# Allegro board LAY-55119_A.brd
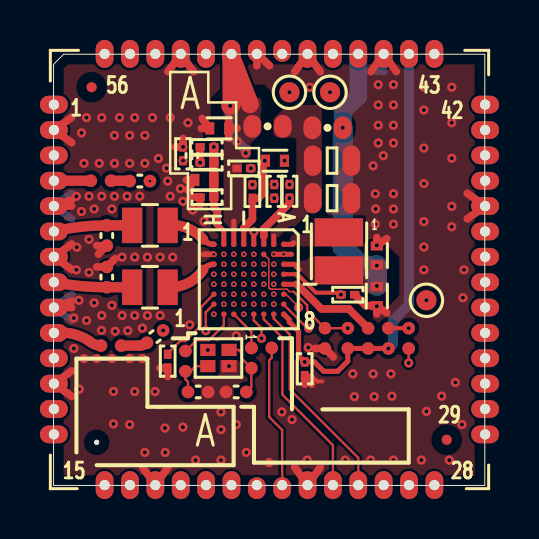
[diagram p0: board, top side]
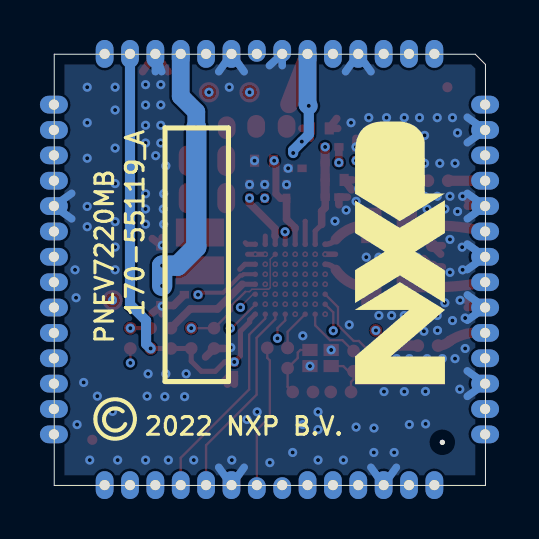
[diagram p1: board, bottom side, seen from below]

Outline 21.59 x 21.59 mm; copper layers: TOP, L2_GND_1, L3_INT_1, L4_INT_2, L5_GND_2, BOTTOM. Coordinates in mm from the lower left corner of the outline.
Outline path: 0,21.08 0,0 21.59,0 21.59,21.59 0.51,21.59 0,21.08

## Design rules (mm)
constraint set DEFAULT: min track width 0.117
net group USB: nets ATX_C ATX_D
net group PWR: nets TCVCM TXVCASC VBAT VDDC VDDIO VDDNV VDDPA VREF

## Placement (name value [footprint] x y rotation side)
C1  18PF  [CC0402_25]  9.14 4.68 180 top
C2  18PF  [CC0402_25]  7.24 4.68 0 top
C5  0.1uF  [CC0201]  5.71 6.22 270 top
C7  1000pF  [CC0402_25]  5.08 7.45 217.3 top
C8  0.1uF  [CC0201]  12.57 5.84 270 top
C9  0.22uF  [CC0201]  14.73 9.55 0 top
C10  4.7uF  [CC0402_TOL0P15]  16.19 9.48 270 top
C11  0.22uF  [CC0201]  11.81 14.73 90 top
C12  560pF  [CC0402_25]  2.67 10.43 90 top
C13  4.7uF  [CC0402_TOL0P15]  16.19 11.51 90 top
C14  560pF  [CC0402_25]  2.67 12.51 270 top
C15  100pF  [CC0201]  7.68 14.43 180 top
C16  0.1uF  [CC0201]  11.05 14.72 90 top
C17  1uf  [CC0201]  9.96 14.72 90 top
C19  22uF  [CC0805_OV]  13.94 14.38 0 top
C20  4.7uF  [CC0402_TOL0P15]  7.55 15.3 180 top
C21  1000pF  [CC0402_25]  4.32 15.24 180 top
C22  100pF  [CC0201]  9.52 15.88 0 top
C23  100pF  [CC0201]  7.68 16.16 0 top
C24  4.7uF  [CC0402_TOL0P15]  11.09 16.26 0 top
C26  0.22uF  [CC0201]  6.48 16.61 90 top
C27  22uF  [CC0805_OV]  13.94 16.26 0 top
C28  0.22uF  [CC0201]  7.68 16.95 0 top
C29  4.7uF  [CC0402_TOL0P15]  8.29 17.88 180 top
L1  160nH  [IND0805HQ]  4.83 9.92 180 top
L2  1.0uH  [IND_1008_SMD]  14.29 11.72 270 top
L3  160nH  [IND0805HQ]  4.83 13.02 180 top
NOREF  -  [unnamed]  1.9 19.94 180 top
NOREF#2  -  [#2]  8.79 5.97 90 top
NOREF#3  -  [unnamed]  19.68 2.29 180 top
NOREF#4  -  [#2]  -53.92 -161.42 0 top
NOREF#5  -  [#2]  16.19 11.04 90 top
NOREF#6  -  [#2]  8.12 15.62 0 top
NOREF#7  -  [#2]  21.61 0.02 90 top
NOREF#8  -  [#2]  7.47 8.02 90 top
NOREF#9  -  [unnamed]  2.16 2.16 270 top
NOREF#10  -  [#2]  7.72 6.78 0 top
NOREF#11  -  [#2]  8.87 18.2 0 top
NOREF#12  -  [#2]  9.28 15.62 90 top
NOREF#13  -  [#2]  9.1 7.03 90 top
NOREF#14  -  [#2]  10.61 16.26 0 top
NOREF#15  -  [#2]  -267.27 261.62 0 top
NOREF#16  -  [#2]  10.18 0.02 0 top
NOREF#17  -  [#2]  -294.83 -257.94 0 top
NOREF#18  -  [#2]  0 0 0 top
NOREF#19  -  [#2]  -27.72 -40.64 0 top
NOREF#20  -  [#2]  21.61 5.1 90 top
NOREF#21  -  [#2]  15.86 10.06 0 top
NOREF#22  -  [#2]  9.1 7.03 0 top
NOREF#23  -  [#2]  11.66 15.93 90 top
NOREF#24  -  [#2]  10.51 15.93 0 top
NOREF#25  -  [#2]  2.16 2.16 0 top
NOREF#26  -  [#2]  0.02 0.02 0 top
NOREF#27  -  [#2]  17.01 10.06 90 top
NOREF#28  -  [#2]  16.51 10.94 0 top
NOREF#29  -  [#2]  7.07 15.3 0 top
NOREF#30  -  [#2]  7.47 8.02 0 top
NOREF#31  -  [#2]  21.61 2.56 90 top
NOREF#32  -  [#2]  17.66 10.94 90 top
NOREF#33  -  [#2]  21.59 0 90 top
NOREF#34  -  [#2]  7.82 17.88 0 top
NOREF#35  -  [#2]  10.02 18.2 90 top
NOREF#36  -  [#2]  16.19 9.01 90 top
NOREF#37  -  [#2]  18.54 3.3 180 bottom
NOREF#38  -  [#2]  2.03 5.08 90 bottom
NOREF#39  -  [#2]  16.55 17.39 270 bottom
P1  PN76xx-M  [MODULE56_1P52_25X25MM_NSP]  10.81 10.81 0 top
R1  0  [RC0402_25]  10.41 6.89 180 top
R2  0  [RC0402_25]  2.88 7 180 top
R3  0  [RC0402_25]  2.37 15.26 180 top
R4  0  [RC0603_OV]  10.72 17.98 180 top
R5  0  [RC0402_25]  15.75 7.37 270 top
R6  0  [RC0402_25]  13.59 7.37 90 top
R7  0  [RC0402_25]  14.73 7.37 90 top
R8  0  [RC0603_OV]  13.72 17.91 180 top
R9  10.0K  [RC0402_25]  16.76 7.37 90 top
R10  0  [RC0402_25]  17.78 7.37 270 top
R11  0  [RC0402_25]  9.91 6.38 270 top
R12  0  [RC0402_25]  6.6 6.22 270 top
TP1  -  [TPAD_040]  13.84 19.68 180 top
TP2  -  [TPAD_040]  11.81 19.68 180 top
TP3  -  [TPAD_040]  18.67 9.27 180 top
U1  PN7220  [VFBGA64_0P5_4P6X4P6]  9.77 10.32 270 top
Y1  27.12MHz  [XTAL4_1P6X1P2]  8.25 6.38 180 top

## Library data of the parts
C1 C2 C7 C10 C12-C14 C19-C21 C24 C27 C29 = CAP_NP
C5 C8 C16 = CAP_NP: Tolerance: TOLERANCE; User Part Number: 150-80059
C9 C11 C26 C28 = CAP_NP: Tolerance: TOLERANCE; User Part Number: 150-79474
C15 C22 C23 = CAP_NP: Tolerance: TOLERANCE; User Part Number: 150-75742
C17 = CAP_NP: Tolerance: TOLERANCE; User Part Number: 150-79855
L1 L3 = INDUCTOR: tolerance: 5%
L2 = INDUCTOR: tolerance: 20%
P1 = TP_RECT_56P
R1-R8 R10-R12 = RES
R9 = RES: tolerance: 5%
TP1-TP3 = TESTLOOP
U1 = PN7220_BGA64_A
Y1 = XTAL_13

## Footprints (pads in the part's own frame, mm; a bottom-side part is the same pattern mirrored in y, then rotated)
CC0201
  rect 0.47x0.381 smd: 1(-0.343,0) 2(0.343,0)
CC0402_25
  round 0.635 smd: 1(-0.508,0) 2(0.508,0)
CC0402_TOL0P15
  rect 0.457x0.61 smd: 1(-0.475,0) 2(0.475,0)
CC0805_OV
  oval 0.889x1.524 smd: 1(-0.965,0) 2(0.965,0)
IND0805HQ
  rect 1.016x1.778 smd: 1(-0.889,0) 2(0.889,0)
IND_1008_SMD
  rect 1.397x2.413 smd: 1(-0.95,0) 2(0.95,0)
MODULE56_1P52_25X25MM_NSP
  oval 1.397x0.889 hole 0.508: 1(-10.795,8.255) 2(-10.795,6.985) 3(-10.795,5.715) 4(-10.795,4.445) 5(-10.795,3.175) 6(-10.795,1.905) 7(-10.795,0.635) 8(-10.795,-0.635) 9(-10.795,-1.905) 10(-10.795,-3.175) 11(-10.795,-4.445) 12(-10.795,-5.715) 13(-10.795,-6.985) 14(-10.795,-8.255) 29(10.795,-8.255) 30(10.795,-6.985) 31(10.795,-5.715) 32(10.795,-4.445) 33(10.795,-3.175) 34(10.795,-1.905) 35(10.795,-0.635) 36(10.795,0.635) 37(10.795,1.905) 38(10.795,3.175) 39(10.795,4.445) 40(10.795,5.715) 41(10.795,6.985) 42(10.795,8.255)
  oval 0.889x1.397 hole 0.508: 15(-8.255,-10.795) 16(-6.985,-10.795) 17(-5.715,-10.795) 18(-4.445,-10.795) 19(-3.175,-10.795) 20(-1.905,-10.795) 23(1.905,-10.795) 24(3.175,-10.795) 25(4.445,-10.795) 26(5.715,-10.795) 27(6.985,-10.795) 28(8.255,-10.795) 43(8.255,10.795) 44(6.985,10.795) 45(5.715,10.795) 46(4.445,10.795) 47(3.175,10.795) 48(1.905,10.795) 51(-1.905,10.795) 52(-3.175,10.795) 53(-4.445,10.795) 54(-5.715,10.795) 55(-6.985,10.795) 56(-8.255,10.795)
  oval 0.889x1.092 hole 0.508: 21(-0.635,-10.795) 22(0.635,-10.795) 49(0.635,10.795) 50(-0.635,10.795)
RC0402_25
  round 0.635 smd: 1(-0.508,0) 2(0.508,0)
RC0603_OV
  oval 0.889x1.143 smd: 1(-0.762,0) 2(0.762,0)
TPAD_040
  round 1.016 smd: 1(0,0)
unnamed
  round 0.508 smd: (0,0)
VFBGA64_0P5_4P6X4P6
  round 0.279 smd: A1(-1.75,1.75) A2(-1.25,1.75) A3(-0.75,1.75) A4(-0.25,1.75) A5(0.25,1.75) A6(0.75,1.75) A7(1.25,1.75) A8(1.75,1.75) B1(-1.75,1.25) B2(-1.25,1.25) B3(-0.75,1.25) B4(-0.25,1.25) B5(0.25,1.25) B6(0.75,1.25) B7(1.25,1.25) B8(1.75,1.25) C1(-1.75,0.75) C2(-1.25,0.75) C3(-0.75,0.75) C4(-0.25,0.75) C5(0.25,0.75) C6(0.75,0.75) C7(1.25,0.75) C8(1.75,0.75) D1(-1.75,0.25) D2(-1.25,0.25) D3(-0.75,0.25) D4(-0.25,0.25) D5(0.25,0.25) D6(0.75,0.25) D7(1.25,0.25) D8(1.75,0.25) E1(-1.75,-0.25) E2(-1.25,-0.25) E3(-0.75,-0.25) E4(-0.25,-0.25) E5(0.25,-0.25) E6(0.75,-0.25) E7(1.25,-0.25) E8(1.75,-0.25) F1(-1.75,-0.75) F2(-1.25,-0.75) F3(-0.75,-0.75) F4(-0.25,-0.75) F5(0.25,-0.75) F6(0.75,-0.75) F7(1.25,-0.75) F8(1.75,-0.75) G1(-1.75,-1.25) G2(-1.25,-1.25) G3(-0.75,-1.25) G4(-0.25,-1.25) G5(0.25,-1.25) G6(0.75,-1.25) G7(1.25,-1.25) G8(1.75,-1.25) H1(-1.75,-1.75) H2(-1.25,-1.75) H3(-0.75,-1.75) H4(-0.25,-1.75) H5(0.25,-1.75) H6(0.75,-1.75) H7(1.25,-1.75) H8(1.75,-1.75)
XTAL4_1P6X1P2
  rect 0.762x0.61 smd: 1(-0.531,-0.405) 2(0.531,-0.405) 3(0.531,0.405) 4(-0.531,0.405)

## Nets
GND: C1.2 C2.2 C5.2 C8.2 C9.2 C10.2 C11.2 C12.2 C13.2 C14.2 C15.2 C16.2 C17.2 C19.2 C20.2 C22.2 C24.2 C26.2 C27.2 C29.2 P1.2 P1.5 P1.7 P1.9 P1.12 P1.17 P1.23 P1.38 P1.45 P1.48 P1.50 P1.53 R6.1 U1.A2 U1.B2 U1.C3 U1.D3 U1.E3 U1.F3 U1.F4 U1.G3 U1.H2 Y1.2 Y1.4
PVDDOUT: R5.1 U1.A5
VBAT: C17.1 C24.1 P1.49 U1.E1
VBATPWR: C10.1 C13.1 L2.2 P1.46 R8.1 U1.A3
VDDBOOST: C19.1 C27.1 R4.1 R8.2 U1.B1
VDDC: C11.1 TP1.1(PIN1) U1.C1
VDDIO: C8.1 P1.44 R5.2 R7.1 R9.1 U1.A8
VDDNV: C9.1 TP3.1(PIN1) U1.A4
VDDPA: C15.1 C20.1 C23.2 C28.2 P1.52 U1.G1
ATX_A: P1.34 U1.E6
ATX_B: P1.35 U1.E5
ATX_C: P1.36 U1.D6
ATX_D: P1.37 U1.D5
AUX1: P1.18 U1.G7
AUX2: P1.19 U1.F7
BOOST_LX: L2.1 U1.A1
C_RXN: C21.2 R3.1
C_RXP: C7.2 R2.1
CLK_IN: P1.22 R1.1
CT_CLK: P1.56 U1.E4
CT_INT: P1.54 U1.C4
CT_IO: P1.55 U1.D4
DWL_REQ: P1.27 U1.A7
GPIO0: P1.28 U1.E8
GPIO1: P1.31 U1.D8
GPIO2: P1.29 U1.E7
GPIO3: P1.30 U1.D7
GPIO4: P1.32 U1.C5
GPIO5: P1.33 U1.B5
HOSTIF_SEL0: P1.20 U1.C7
HOSTIF_SEL1: P1.21 U1.C6
I2CM_SCL: P1.40 U1.B6
I2CM_SDA: P1.39 U1.A6
IRQ: P1.26 U1.B7
MOD_RXN: P1.4 R3.2
MOD_RXP: P1.10 R2.2
MOD_TX1: C14.1 L3.2 P1.6
MOD_TX2: C12.1 L1.2 P1.8
MOD_VEN: P1.43 R10.2
NO_AD1: P1.1 U1.E2
NO_TEST: R6.2 R7.2 U1.C2
NO_USB_VBUS: P1.47 U1.D1
PRD1: P1.41 U1.B4
PRD2: P1.42 U1.G4
RXN: C21.1 U1.H4
RXP: C7.1 U1.H5
SPIM_MISO: P1.16 U1.F6
SPIM_MOSI: P1.13 U1.F5
SPIM_NSS: P1.15 U1.G6
SPIM_SCLK: P1.14 U1.G5
SWDCLK: P1.24 U1.C8
SWDIO: P1.25 U1.B8
TCVCM: C26.1 U1.G2
TX1: L3.1 U1.H1
TX2: L1.1 U1.H3
TXVCASC: C23.1 C28.1 U1.F2
VEN: R9.2 R10.1 U1.B3
VMID: C5.1 U1.H6
VREF: C16.1 TP2.1(PIN1) U1.D2
VTUNE0: P1.3 U1.H8
VTUNE1: P1.11 U1.H7
VUP: C22.1 C29.1 P1.51 R4.2 U1.F1
XTAL1: R1.2 R11.1 U1.F8
XTAL2: R12.1 U1.G8(XTAL2)
N26294688: C1.1 R11.2 Y1.1
N26294692: C2.1 R12.2 Y1.3

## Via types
v1: diameter 0.457, hole 0.203, TOP to BOTTOM, 140 vias
v2: diameter 0.457, hole 0.206, TOP to BOTTOM, 28 vias
v3: diameter 0.279, hole 0.13, TOP to L2_GND_1, 42 vias
v4: diameter 0.254, hole 0.13, L2_GND_1 to L3_INT_1, 33 vias
v5: diameter 0.279, hole 0.13, L3_INT_1 to L4_INT_2, 16 vias

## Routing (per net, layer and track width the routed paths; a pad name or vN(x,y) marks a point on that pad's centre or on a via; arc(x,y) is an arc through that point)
GND: length 140.5
  TOP w0.203: C8.2 12.92,5.5 13.21,5.21 13.46,5.21
  TOP w0.254: 11.91,11.57 v3(11.52,11.57) v3(11.02,11.57)
  TOP w0.279: v3(8.02,11.57) 7.51,11.57
  TOP w0.381: 6.66,15.3 C20.2 6.7,14.8 ; 2.24,11.58 C14.2 2.16,12.01 ; 13.35,20.72 P1.48 12.08,20.72 ; 13.35,0.91 P1.23 12.08,0.91 ; 16.68,12.36 C13.2 16.19,12.41 ; 5.73,0.91 P1.17 4.46,0.91 ; 13.08,6.86 R6.1 14.01,6.43 ; 0.91,12.08 P1.7 0.91,10.81 ; 7.4,17.88 C29.2 7.45,18.37 ; C9.2 15.62,9.01 C10.2 ; 12.92,5.07 C8.2 12.57,5.07 ; 5.71,5.45 C5.2 5.33,5.88 ; 0.91,9.22 P1.9 0.91,8.91 ; 5.73,20.72 P1.53 7,20.72 ; 20.72,13.35 P1.38 20.72,14.62 ; 0.91,5.73 P1.12 0.91,4.46 ; 16.19,8.59 C10.2 ; C10.2 16.68,8.63 ; 17.16,20.72 P1.45 15.89,20.72 ; 0.91,13.99 P1.5 0.91,14.3 ; 10.18,21.02 P1.50 10.81,21.02 ; 2.16,10.94 C12.2 3.09,11.36 ; 6.48,17.38 v2(6.48,16.95) 6.1,16.95 ; 6.91,14.43 C15.2 7.34,14.05 ; 0.91,17.16 P1.2 0.91,18.43
  L2_GND_1 w0.381: 0.91,12.08 P1.7 0.91,10.81 ; 13.35,20.72 P1.48 12.08,20.72 ; 20.72,13.35 P1.38 20.72,14.62 ; 0.91,18.43 P1.2 0.91,17.16 ; 0.91,4.46 P1.12 0.91,5.73 ; 4.46,0.91 P1.17 5.73,0.91 ; 7,20.72 P1.53 5.73,20.72 ; 10.18,21.02 P1.50 10.81,21.02 ; 0.91,9.54 P1.9 0.91,8.27 ; 12.08,0.91 P1.23 13.35,0.91 ; 17.16,20.72 P1.45 15.89,20.72 ; 0.91,14.62 P1.5 0.91,13.35
  L4_INT_2 w0.381: 10.18,21.02 P1.50 9.86,21.02 ; 20.72,13.35 P1.38 20.72,14.62 ; 0.91,5.73 P1.12 0.91,4.46 ; 6.37,20.72 P1.53 5.73,20.72 ; 0.91,10.81 P1.7 0.91,12.08 ; 17.16,20.72 P1.45 15.89,20.72 ; 0.91,14.62 P1.5 0.91,13.35 ; 0.91,8.27 P1.9 0.91,9.54 ; 5.73,0.91 P1.17 4.46,0.91 ; 13.35,0.91 P1.23 12.08,0.91 ; 0.91,17.16 P1.2 0.91,18.43 ; 13.35,20.72 P1.48 12.72,20.72
  L5_GND_2 w0.381: 0.91,8.27 P1.9 0.91,9.54 ; 0.91,14.62 P1.5 0.91,13.35 ; 17.16,20.72 P1.45 15.89,20.72 ; 4.46,0.91 P1.17 5.73,0.91 ; 0.91,12.08 P1.7 0.91,10.81 ; 13.35,20.72 P1.48 12.08,20.72 ; 13.35,0.91 P1.23 12.08,0.91 ; 0.91,4.46 P1.12 0.91,5.73 ; 7,20.72 P1.53 5.73,20.72 ; 20.72,14.62 P1.38 20.72,13.35 ; 10.81,21.02 P1.50 10.18,21.02 ; 0.91,18.43 P1.2 0.91,17.16
  BOTTOM w0.381: 5.73,20.72 P1.53 7,20.72 ; 16.21,20.72 P1.45 16.53,20.72 ; 4.46,0.91 P1.17 5.73,0.91 ; 0.91,5.73 P1.12 0.91,4.46 ; 20.72,14.62 P1.38 20.72,13.35 ; 12.08,20.72 P1.48 13.35,20.72 ; 10.18,21.02 P1.50 10.81,21.02 ; 0.91,9.54 P1.9 0.91,8.27 ; 0.91,10.81 P1.7 0.91,12.08 ; 13.35,0.91 P1.23 12.08,0.91 ; 0.91,13.35 P1.5 0.91,14.62 ; 0.91,17.16 P1.2 0.91,18.43
  vias: v1(1.02,8.38) v1(1.02,6.86) v1(1.14,14.48) v1(1.17,11.93) v1(1.14,10.79) v1(1.27,9.27) v1(1.28,4.82) v1(1.4,17.65) v1(1.4,13.72) v1(1.52,16.13) v1(1.52,6.35) v1(1.65,18.41) v1(1.65,8.25) v1(1.78,14.48) v1(1.78,12.32) v1(1.78,10.67) v1(2.03,13.84) v1(2.03,9.14) v1(2.16,6.35) v1(2.29,16.13) v1(2.4,7.76) v1(2.41,18.41) v1(2.41,14.48) v1(2.41,8.51) v1(2.92,13.84) v1(2.92,9.02) v1(2.92,6.35) v1(3,4.71) v1(3,3.08) v1(3.05,17.53) v1(3.05,16.13) v1(3.05,14.48) v1(3.08,7.72) v1(3.3,18.41) v1(3.43,11.43) v1(3.43,8.51) v1(3.68,14.48) v1(3.72,7.75) v1(3.81,17.53) v1(3.81,16.13) v1(3.81,6.35) v1(3.81,3.05) v1(4.06,18.41) v1(4.06,11.43) v1(4.06,8.51) v1(4.06,4.7) v1(4.32,14.48) v1(4.45,7.87) v1(4.45,6.35) v1(4.57,17.53) v1(4.57,16.13) v1(4.57,1.65) v1(4.7,11.43) v1(4.7,8.51) v1(4.95,18.41) v1(5.08,4.7) v1(5.25,16.37) v1(5.33,11.43) v1(5.33,8.51) v1(5.58,2.87) v1(5.59,1.65) v1(5.66,15.88) v1(5.71,15.24) v1(5.84,18.41) v1(5.84,14.48) v1(5.97,11.43) v1(6.35,14.86) v1(6.48,14.22) v1(6.48,2.92) v1(6.73,18.16) v1(6.82,8.04) v1(6.97,13.79) v1(7.11,1.27) v1(7.53,13.23) v1(8.38,3.68) v1(8.38,2.79) v1(8.38,1.27) v1(9.14,7.49) v1(9.14,3.05) v1(9.65,1.65) v1(10.79,1.14) v1(11.43,3.68) v1(11.94,3.3) v1(12.7,1.27) v1(12.75,6.91) v1(12.83,19.94) v1(14.61,1.27) v1(14.99,5.59) v1(15.06,4.45) v1(15.88,1.27) v1(16,16) v1(16,5.59) v1(16.05,4.45) v1(16.11,14.6) v1(16.13,13.84) v1(16.11,13.08) v1(16.26,20.07) v1(16.26,19.05) v1(16.26,18.03) v1(16.26,17.14) v1(16.51,16.51) v1(16.89,5.59) v1(16.94,4.47) v1(17.02,20.07) v1(17.02,19.05) v1(17.02,18.03) v1(17.02,17.14) v1(17.02,14.61) v1(17.02,13.84) v1(17.02,13.08) v1(17.02,1.27) v1(18.41,1.27) v1(18.54,19.94) v1(18.54,18.8) v1(18.54,16.89) v1(18.54,15.11) v1(18.54,13.21) v1(18.54,11.94) v1(18.54,10.79) v1(18.67,3.71) v1(19.43,4.47) v1(19.81,1.27) v1(19.94,19.94) v1(19.94,18.16) v1(19.94,16.38) v1(19.94,13.97) v1(19.94,12.95) v1(20.12,5.16) v1(20.5,9.4) v1(20.45,3.05) v1(20.55,10.79) v2(7.72,6.78) v2(8.79,5.97) v2(9.88,15.88) v2(9.96,15.06) v2(11.05,15.07) v2(11.56,16.26) v2(11.81,15.06) v2(16.19,12.02) v2(16.19,8.97) v3(8.53,11.07) v3(9.02,11.07) v3(9.02,10.57) v3(9.52,11.07) v3(10.02,11.07) v3(10.52,11.07)
PVDDOUT: length 5.1
  TOP w0.117: 12.18,10.07 12.09,10.07
  TOP w0.254: 12.09,10.07 U1.A5
  TOP w0.381: R5.1 14.78,8.84 13.41,8.84 12.18,10.07
VBAT: length 10.6
  TOP w0.254: 9.54,12.85 9.52,12.83 U1.E1
  TOP w0.356: C17.1 10.27,14.38 10.49,14.6 10.49,16.14 C24.1 v2(10.58,16.26)
  TOP w0.381: C17.1 9.96,13.32 9.54,12.91 9.54,12.85
  L4_INT_2 w0.508: v2(10.58,16.26) 10.79,16.48 10.79,20.07 11.45,20.72 P1.49
VBATPWR: length 27.1
  TOP w0.254: U1.A3 12.05,11.07 12.3,10.82
  TOP w0.381: C13.1 16.2,11.05
  L3_INT_1 w0.889: v2(14.48,17.91) 14.48,18.71 15.26,19.49 P1.46
  L3_INT_1 w1.016: v2(14.48,17.91) 14.48,11.94 15.41,11.01 v2(16.19,11.01) v2(16.19,9.99)
  BOTTOM w0.889: P1.46 15.26,19.49 14.48,18.71 v2(14.48,17.91)
  BOTTOM w1.016: v2(14.48,17.91) 14.48,11.94 15.41,11.01 v2(16.19,11.01) v2(16.19,9.99)
VDDBOOST: length 0.4
  TOP w0.254: U1.B1 11.02,12.49
VDDC: length 9
  TOP w0.254: U1.C1 10.52,12.49
  TOP w0.381: v2(11.81,14.38) 11.81,14.13 10.53,12.85 10.53,12.49 10.52,12.49
  L4_INT_2 w0.203: v2(11.81,14.38) 12.85,15.42 12.85,18.69 v2(13.84,19.68)
VDDIO: length 23.2
  TOP w0.254: v2(16.76,6.86) R5.2 R7.1 14.73,6.22 14.22,5.71 13.53,5.71 13.06,6.18 v2(12.57,6.18) 12.27,6.49 12.27,7.72 11.8,8.19 11.8,8.3 U1.A8
  BOTTOM w0.508: v2(16.76,6.86) 16.99,7.09 16.99,8.25 17.8,9.06 P1.44
VDDNV: length 8.4
  TOP w0.203: U1.A4 12.12,10.57 12.18,10.51 12.27,10.51 13.13,9.65 14.29,9.65 v2(14.39,9.55)
  L3_INT_1 w0.203: v2(18.67,9.27) 17.78,8.38 15.56,8.38 v2(14.39,9.55)
VDDPA: length 9.9
  TOP w0.254: 8.2,13.07 8.53,12.74 U1.G1
  TOP w0.381: C15.1 8.02,13.91 8.2,13.73 8.2,13.07
  TOP w0.457: C15.1 C20.1 C23.2 v2(8.02,16.95)
  L4_INT_2 w0.508: v2(8.02,16.95) 7.64,17.34 P1.52
ATX_A: length 21.4
  L4_INT_2 w0.076: 10.81,8.29 v5(9.52,9.57)
  L4_INT_2 w0.102: P1.34 20.78,8.91 20.68,8.81 20.68,4.93 18.75,3 12.85,3 11.13,4.72 11.13,7.97 10.81,8.29
ATX_B: length 19.3
  L3_INT_1 w0.102: P1.35 20.49,10.18 19.58,9.27 19.58,7.42 v5(18.72,6.55)
  L4_INT_2 w0.076: 13,8.29 12.96,8.33 12.25,8.33 10.16,10.41 9.87,10.41 v5(9.52,10.07)
  L4_INT_2 w0.102: 13,8.29 13.23,8.06 13.23,7.41 13.36,7.28 13.36,5.94 14.43,4.88 17.68,4.88 18.72,5.92 v5(18.72,6.55)
ATX_C: length 22.8
  L4_INT_2 w0.107: P1.36 20.73,11.45 20.62,11.55 20.62,11.82 20.51,11.93 20.36,11.93 19.99,11.56 19.99,5.84 17.83,3.68 13.31,3.68 11.73,5.26 11.73,8 10.16,9.57 v5(10.02,9.57)
ATX_D: length 22.8
  L4_INT_2 w0.107: P1.37 20.73,12.72 20.62,12.61 20.62,12.34 20.51,12.24 20.24,12.24 19.68,11.69 19.68,5.97 17.7,3.99 13.44,3.99 12.04,5.39 12.04,8.13 10.24,9.93 10.16,9.93 v5(10.02,10.07)
AUX1: length 10.1
  L3_INT_1 w0.076: v4(8.53,9.07) 8.53,8.29
  L3_INT_1 w0.102: P1.18 6.37,1.67 6.98,2.29 6.98,5.36 7.72,6.1 7.99,6.1 8.28,6.38 8.28,7.62 8.53,7.86 8.53,8.29
AUX2: length 9.6
  L3_INT_1 w0.076: v4(9.02,9.07) 9.02,8.29
  L3_INT_1 w0.102: 9.02,8.29 9.02,7.98 8.51,7.47 8.51,6.29 8.13,5.91 8.13,5.49 7.64,5 P1.19
BOOST_LX: length 0.5
  TOP w0.254: U1.A1 11.95,12.07 12.02,12.15
C_RXN: length 0.9
  TOP w0.516: R3.1 3.79,15.26 3.81,15.24
C_RXP: length 1.3
  TOP w0.516: R2.1 4.33,7 arc(4.52,7.04) C7.2
CLK_IN: length 7.2
  TOP w0.117: P1.22 11.45,2.78 10.79,3.43 10.79,6.26 10.92,6.38 R1.1
CT_CLK: length 19.9
  L3_INT_1 w0.076: v4(9.52,10.57) 10.89,11.94 11.23,11.94 12.4,13.11 12.4,13.11
  L3_INT_1 w0.102: 12.4,13.11 12.4,16.33 9,19.72 3.14,19.72 2.56,20.3 P1.56
CT_INT: length 18.1
  L3_INT_1 w0.076: 13.16,13.11 13.16,13.03 11.56,11.43 11,11.43 10.52,10.96 v4(10.52,10.57)
  L3_INT_1 w0.102: 13.16,13.11 13.16,16.56 9.27,20.45 5.33,20.45 5.1,20.68 P1.54
CT_IO: length 19.1
  L3_INT_1 w0.076: v4(10.02,10.57) 10.02,10.74 10.97,11.68 11.37,11.68 12.8,13.11
  L3_INT_1 w0.102: P1.55 3.83,20.3 4.06,20.07 9.14,20.07 12.8,16.41 12.8,13.11
DWL_REQ: length 12
  TOP w0.076: 11.62,8.95 11.52,9.05 U1.A7
  TOP w0.117: 11.62,8.95 12.7,7.87 v1(12.77,7.87)
  L3_INT_1 w0.102: P1.27 17.8,1.63 16.89,2.54 16.31,2.54 13.73,5.12 13.73,6.91 v1(12.77,7.87)
GPIO0: length 17.4
  L3_INT_1 w0.076: 9.52,8.29 v4(9.52,8.57)
  L3_INT_1 w0.102: 9.52,8.29 9.52,6.05 v5(8.85,5.38)
  L4_INT_2 w0.102: v5(8.85,5.38) 8.85,4.15 11.33,1.68 18.64,1.68 19.07,1.25 P1.28
GPIO1: length 17.4
  TOP w0.117: U1.D8 10.02,8.26 10.41,7.87 v1(10.41,7.37)
  L4_INT_2 w0.102: P1.31 20.83,4.32 20.5,4.32 18.87,2.69 11.79,2.69 10.54,3.94 10.54,6.83 10.41,6.96 v1(10.41,7.37)
GPIO2: length 18.3
  L3_INT_1 w0.076: v4(9.52,9.07) 9.8,8.79 9.8,8.29
  L3_INT_1 w0.102: 9.8,8.29 9.8,6.32 9.98,6.15 9.98,5.61 9.86,5.49 v5(9.86,5.23)
  L4_INT_2 w0.102: P1.29 20.08,2.56 19.51,1.98 11.63,1.98 9.86,3.76 v5(9.86,5.23)
GPIO3: length 18
  L3_INT_1 w0.076: 10.03,8.29 10.03,8.41 10.02,8.42 v4(10.02,9.07)
  L3_INT_1 w0.102: v5(10.22,6.48) 10.22,6.49 10.03,6.68 10.03,8.29
  L4_INT_2 w0.102: v5(10.22,6.48) 10.22,3.82 11.73,2.31 19.08,2.31 20.59,3.83 P1.30
GPIO4: length 15.2
  L3_INT_1 w0.076: 13.2,8.29 12.67,8.81 12.67,9.12 11.96,9.83 10.77,9.83 v4(10.52,10.07)
  L3_INT_1 w0.102: P1.32 20.59,6.37 19.1,4.88 14.55,4.88 13.96,5.47 13.96,7.53 13.2,8.29
GPIO5: length 15
  L3_INT_1 w0.076: v4(11.02,10.07) 12.15,10.07 12.95,9.27 12.95,8.97 13.21,8.71
  L3_INT_1 w0.102: P1.33 20.67,7.64 18.19,5.16 14.76,5.16 14.25,5.66 14.25,7.67 13.21,8.71
HOSTIF_SEL0: length 10.2
  L3_INT_1 w0.076: v4(10.52,9.07) 10.52,8.35 10.58,8.29
  L3_INT_1 w0.102: P1.20 8.91,1.92 9.86,2.87 9.86,4.78 10.44,5.36 10.44,6.2 11.07,6.83 11.07,7.8 10.58,8.29
HOSTIF_SEL1: length 10.5
  L3_INT_1 w0.076: v4(10.52,9.57) 10.77,9.33 10.77,8.74 11.22,8.29
  L3_INT_1 w0.102: P1.21 10.18,4.36 10.69,4.88 10.69,6.12 11.51,6.93 11.51,8 11.22,8.29
I2CM_SCL: length 20.9
  L3_INT_1 w0.076: v5(11.51,9.57) v4(11.02,9.57)
  L4_INT_2 w0.076: v5(11.51,9.57) 12.3,9.57 13.05,8.82 13.21,8.82
  L4_INT_2 w0.102: 13.21,8.82 13.33,8.82 13.84,8.31 13.84,8.03 15.65,6.22 17.14,6.22 17.65,6.73 17.91,6.73 18.54,7.37 18.54,8.48 18.08,8.94 18.08,13.89 20.72,16.53 P1.40
I2CM_SDA: length 21.5
  TOP w0.076: v1(12.27,8.92) 12.27,8.94 11.64,9.57 U1.A6
  L4_INT_2 w0.076: v1(12.27,8.92) 12.28,8.92 12.39,8.92 12.72,8.59 13.13,8.59 13.21,8.51
  L4_INT_2 w0.102: 13.21,8.51 13.53,8.19 13.53,7.9 13.69,7.75 13.69,6.12 14.63,5.18 17.5,5.18 18.34,6.02 18.34,6.71 18.85,7.21 18.85,8.74 19.18,9.07 19.18,14.1 20.34,15.26 P1.39
IRQ: length 11.3
  L3_INT_1 w0.076: 11.81,8.29 v4(11.02,9.07)
  L3_INT_1 w0.102: 11.81,8.29 11.89,8.21 11.89,6.05 16.53,1.41 P1.26
MOD_RXN: length 1.8
  TOP w0.516: R3.2 P1.4
MOD_RXP: length 2.5
  TOP w0.516: R2.2 arc(2.05,7.06) 1.78,7.24 1.78,7.24 arc(0.93,7.59) P1.10
MOD_TX1: length 3.9
  TOP w0.516: L3.2 C14.1 arc(1.33,12.95) P1.6
MOD_TX2: length 3.9
  TOP w0.516: L1.2 C12.1 arc(1.34,9.99) P1.8
MOD_VEN: length 16.8
  TOP w0.117: R10.2 v1(17.78,6.13)
  L3_INT_1 w0.102: P1.43 19.07,19.67 19.18,19.56 19.18,7.53 v1(17.78,6.13)
NO_AD1: length 15.5
  L3_INT_1 w0.076: 9.52,13.11 v4(9.52,11.57)
  L3_INT_1 w0.102: 9.52,13.11 9.52,15.27 8.51,16.28 8.51,17.45 6.89,19.07 P1.1
NO_TEST: length 6.7
  TOP w0.071: 10.78,11.32 10.78,9.9
  TOP w0.076: 12.02,9.7 11.81,9.7 11.69,9.82 10.93,9.82 10.93,9.82 10.85,9.82 10.78,9.9 ; U1.C2 10.78,11.32
  TOP w0.117: v2(14.73,7.87) R6.2 13.58,7.87 12.7,8.75 12.7,9.02 12.02,9.7
NO_USB_VBUS: length 12.9
  TOP w0.254: U1.D1 10.02,12.69 v1(10.03,12.7)
  L4_INT_2 w0.508: P1.47 13.99,21.19 15.19,19.99 15.19,16.56 11.33,12.7 v1(10.03,12.7)
PRD1: length 21.5
  L4_INT_2 w0.076: 13.21,10.06 12.69,10.57 v5(11.02,10.57)
  L4_INT_2 w0.102: P1.41 20.34,17.8 17.68,15.14 17.68,8.74 18.24,8.18 18.24,7.49 18.14,7.39 15.88,7.39 13.21,10.06
PRD2: length 17.1
  L3_INT_1 w0.076: v5(8.77,11.3) 8.77,10.82 v4(8.53,10.57)
  L4_INT_2 w0.076: v5(8.77,11.3) 8.98,11.08 8.99,11.07 10.24,11.07 10.69,11.53 11.91,11.53 13.21,12.83
  L4_INT_2 w0.102: P1.42 19.88,19.07 14.02,13.21 13.59,13.21 13.21,12.83
RXN: length 5.8
  L3_INT_1 w0.279: v4(8.02,10.57) arc(7.74,10.63) 7.49,10.79
  L3_INT_1 w0.533: 7.49,10.79 7.12,11.16 arc(5.78,12.9) 4.92,14.91 v4(4.83,15.24)
RXP: length 3.5
  L3_INT_1 w0.279: 7.11,9.23 7.91,10.03 arc(7.96,10.06) v4(8.02,10.07)
  L3_INT_1 w0.516: v2(5.48,7.76) 5.92,8.2 6.08,8.2 7.11,9.23
SPIM_MISO: length 12.6
  L4_INT_2 w0.076: 9.55,8.29 9.55,9.05 v5(9.02,9.57)
  L4_INT_2 w0.102: 9.55,8.29 9.55,7.32 9.31,7.09 9.12,7.09 8.24,6.21 8.24,5.6 5.92,3.28 5.31,3.28 3.83,1.8 P1.16
SPIM_MOSI: length 12.2
  L4_INT_2 w0.076: v5(9.02,10.07) 8.63,10.07 8.25,9.7 8.25,8.88 7.74,8.36
  L4_INT_2 w0.102: 7.74,8.36 7.6,8.36 7.39,8.15 7.39,8.02 7.26,7.89 7.26,7.89 6.96,7.58 6.96,7.52 4.98,5.54 2.79,5.54 1.08,3.83 P1.13
SPIM_NSS: length 12.7
  L4_INT_2 w0.076: v5(8.53,9.57) 8.89,9.21 8.89,8.29
  L4_INT_2 w0.102: 8.89,8.29 8.89,7.74 8.79,7.64 8.79,7.59 8.15,6.95 8.15,6.56 7.87,6.28 7.87,5.82 5.69,3.63 5.03,3.63 2.56,1.16 P1.15
SPIM_SCLK: length 14
  L3_INT_1 w0.076: 8.28,8.41 8.28,8.69 8.25,8.71 8.25,9.68 8.53,9.95 v4(8.53,10.07)
  L3_INT_1 w0.102: 8.28,8.41 8.1,8.23 8.1,7.59 7.75,7.24 7.24,7.24 7.1,7.1 v5(7.1,6.36)
  L4_INT_2 w0.102: P1.14 1.16,2.56 2.57,3.96 5.59,3.96 7.32,5.7 7.32,6.14 v5(7.1,6.36)
SWDCLK: length 10
  TOP w0.117: P1.24 13.99,2.01 11.46,4.54 11.46,7.39 10.52,8.32 U1.C8
SWDIO: length 10.3
  TOP w0.117: U1.B8 11.02,8.36 11.83,7.55 11.83,4.81 15.26,1.38 P1.25
TCVCM: length 5.5
  L3_INT_1 w0.076: 8.41,13.11 8.41,12.88 8.53,12.76 v4(8.53,11.57)
  L3_INT_1 w0.203: 8.41,13.11 8.41,14.34 v2(6.48,16.26)
TX1: length 2.6
  TOP w0.279: 7.49,12.32 arc(7.73,12.14) U1.H1
  TOP w0.516: L3.1 arc(6.69,12.89) 7.49,12.32
TX2: length 2.7
  TOP w0.279: 7.49,10.79 arc(7.72,11) U1.H3
  TOP w0.516: L1.1 arc(6.72,10.13) 7.49,10.79
TXVCASC: length 6.1
  TOP w0.381: C28.1 v2(7.34,16.16)
  L3_INT_1 w0.203: v4(9.02,11.57) 8.89,11.71 8.89,14.61 v2(7.34,16.16)
VEN: length 9.4
  TOP w0.203: R9.2 v2(17.78,7.87)
  L4_INT_2 w0.203: v2(17.78,7.87) 16.38,7.87 15.62,8.64 15.62,9.19 13.74,11.07 v5(11.02,11.07)
VMID: length 4.1
  TOP w0.117: U1.H6 7.38,8.93 7.38,8.02 7.26,7.9 7.26,7.89 6.6,7.23 6.34,7.23 5.71,6.61 C5.1
VREF: length 10.4
  L3_INT_1 w0.254: v4(10.02,11.57) 10.02,11.59 10.36,11.93
  L3_INT_1 w0.381: 10.36,11.93 11.05,12.61 v2(11.05,14.38)
  L4_INT_2 w0.203: v2(11.81,19.68) 12.4,19.1 12.4,16.08 11.89,15.57 10.74,15.57 10.54,15.37 10.54,14.89 v2(11.05,14.38)
VTUNE0: length 15.3
  L3_INT_1 w0.076: v4(8.02,8.57) 8.02,9.68 8.28,9.93 8.28,12.7 8,12.98 8,13.11
  L3_INT_1 w0.102: 8,13.11 8,14.15 5.84,16.31 5.84,16.64 5.59,16.89 1.4,16.89 1.03,16.53 P1.3
VTUNE1: length 10.5
  TOP w0.117: v1(7.62,7.75) 7.62,8.67 U1.H7
  L3_INT_1 w0.102: v1(7.62,7.75) 7.21,7.75 6.87,7.4 6.87,7.12 5.33,5.59 1.65,5.59 0.87,6.37 P1.11
VUP: length 15.8
  TOP w0.254: U1.F1 9.02,13.22 9.02,13.22
  TOP w0.381: C29.1 9.19,17.88 ; C29.1 8.77,18.37 ; C29.1 8.77,17.38
  TOP w0.889: 9.83,19.08 8.87,21.53 P1.51 8.91,19.07 v1(8.85,19.01)
  L4_INT_2 w0.889: v1(8.85,19.01) 8.91,19.07 P1.51
  BOTTOM w0.508: v1(8.85,19.01) 8.85,17.57 v1(9.19,17.22) 9.63,16.78 v1(9.63,16.64)
  BOTTOM w0.889: v1(8.85,19.01) 8.91,19.07 P1.51
XTAL1: length 2.1
  TOP w0.117: R11.1 9.91,7.69 U1.F8
XTAL2: length 3
  TOP w0.117: R12.1 6.74,6.86 6.75,6.86 7.16,7.27 7.78,7.27 8.53,8.02 U1.G8
N26294688: length 3
  TOP w0.117: Y1.1 9.27,6.78 9.4,6.65 9.4,6.38 R11.2 9.91,4.94 C1.1
N26294692: length 2.3
  TOP w0.117: C2.1 6.73,5.18 6.6,5.31 6.6,5.67 6.65,5.71 ; 6.65,5.71 R12.2 ; 6.65,5.71 6.86,5.71 7.12,5.97 Y1.3

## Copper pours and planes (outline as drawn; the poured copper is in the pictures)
GND on TOP: 21.08,0.51 0.51,0.51 0.51,20.87 0.72,21.08 21.08,21.08 ; 4 cut-outs
GND on BOTTOM, L2_GND_1, L5_GND_2: 21.08,0.51 0.51,0.51 0.51,20.87 0.72,21.08 21.08,21.08
GND on L4_INT_2: 21.08,0.51 0.51,0.51 0.51,20.87 0.72,21.08 21.08,21.08 ; 9 cut-outs
VBATPWR on TOP: 12.25,11.27 12.64,11.27 12.85,11.47 15.86,11.47 15.98,11.35 16.49,11.35 16.68,11.16 16.68,9.78 16.51,9.61 15.56,9.61 15.47,9.7 15.47,10.01 15.41,10.07 12.61,10.07 12.12,10.56 12.12,11.14
VDDBOOST on TOP: 12.16,14.04 10.85,12.73 10.85,12.51 10.93,12.43 11.27,12.43 11.82,12.98 12.09,12.98 13.44,14.33 13.44,18.82 13.21,19.05 11.7,19.05 11,18.35 11,17.59 11.18,17.41 12.06,17.41 12.16,17.31
BOOST_LX on TOP: 15.5,11.97 15.5,13.4 13.06,13.4 13,13.34 13,12.79 12.78,12.57 11.99,12.57 11.85,12.44 11.85,12.03 11.91,11.97
VUP on TOP: 10.39,18.54 10.39,17.63 9.86,17.09 9.86,16.46 9.52,16.13 9.52,13.21 9.02,12.7 8.51,13.21 8.51,19.13 8.81,19.43 10.29,19.43 10.4,19.32 10.4,18.55

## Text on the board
BOTTOM: 9 OF 11 | L6_SS
Board Geometry/Soldermask Bottom: 10 OF 11 | SECONDARY SOLDERMASK
Ref Des/Silkscreen Bottom: 170-55119_A | PNEV7220MB | 11 OF 11 | SECONDARY SILKSCREEN
User.Comments: 1 OF 1 | TEST PROBE | 1/1 | 1 | 2
TOP: 4 OF 11 | L1_PS
Board Geometry/Soldermask Top: 3 OF 11 | PRIMARY SOLDERMASK
Ref Des/Silkscreen Top: 2 OF 11 | PRIMARY SILKSCREEN | A
L2_GND_1: 5 0F 11 | L2_GND_1
L3_INT_1: 6 OF 11 | L3_INT_1
L4_INT_2: 7 OF 11 | L4_INT_2
L5_GND_2: 8 OF 11 | L5_GND_2
XSECTION_CHART: SCALE: NONE | *  SURFACE - AIR 0 MIL | *  DIELECTRIC - DRY_FILM_MASK 0.42 MIL | L1 TOP CONDUCTOR - 1/2OZ_COPPER_PLATED 0.35 MIL | *  DIELECTRIC - FR-4 2.95 MIL | L2 L2_GND_1 PLANE - 1/2OZ_COPPER 0.6 MIL | *  DIELECTRIC - FR-4 4 MIL | L3 L3_INT_1 CONDUCTOR - 1/2OZ_COPPER 0.6 MIL | *  DIELECTRIC - FR-4 13.58 MIL | L4 L4_INT_2 CONDUCTOR - 1/2OZ_COPPER 0.6 MIL | L5 L5_GND_2 PLANE - 1/2OZ_COPPER 0.6 MIL | L6 BOTTOM CONDUCTOR - 1/2OZ_COPPER_PLATED 0.35 MIL | DESIGN CROSS SECTION CHART | ___________________________ | TOTAL THICKNESS 31.42 MIL | 1-6 | 1-2 | 2-3 | 3-4 | 23. PLATED HALF HOLES(CASTELLATION HOLES) 56 POS. | TYPE: LPI OR EQUIVALENT. | A. LOCATION = +/-.002" OF PLATED PADS. | B. DIAMETER OR SIZE = +/-.002 OF ORIGINAL DATA | CASTELLATION HOLES | 22 | 23 | 21 | 18 | 56x PLACES | DETAIL | LAYER STACKUP | A
DIMENSION: PRIMARY DATUM | GRID ORIGIN
BODY_CENTER: 1 OF 11 | PASTEMASK TOP
PASTEMASK_BOTTOM: 12 OF 12 | SECONDARY PASTEMASK
User.9: PIN14 | PIN1 | SPIM_MOSI | SPIM_SCLK | MOD_RXN | GND | MOD_TX2 | MOD_RXP | MOD_TX1 | VTUNE1 | VTUNE2 | AD1 | I2CM_SDA | PRD1 | I2CM_SCL | PRD2 | ATX_A | ATX_C | GPIO4 | GPIO1 | ATX_B | ATX_D | GPIO3 | GPIO2 | GPIO5 | CT_CLK | SPIM_NSS | CT_IO | SPIM_MISO | CT_INT | AUX1 | AUX2 | VDDPA | HOSTIF_SEL0 | VUP | HOSTIF_SEL1 | CLK_IN | VBAT | USB_VBUS | SWDCLK | VBATPWR | SWDIO | IRQ | VDDIO | DWL_REQ | VEN-R10- | GPIO0
User.15: 22. THIS FAB_VIAFILL.ART SHOWS LOCATIONS OF VIA-IN-PAD TO BE FILLED." | 1/1 | 2 | FAB SUPPLIER: DISREGARD THIS PAGE IF VIA-IN-PAD DOESN'T APPLY OR NOT REQUIRED ON FAB.ART
User.16: ALL PARTS, MATERIALS AND FINISHED | ASSEMBLY SHALL NOT CONTAIN ANY OF | THE SUBSTANCES OF VERY HIGH CONCERN | (SVHC) ABOVE THE THRESHOLD VALUE PER | THE CURRENT ECHA LIST OF SVHC'S AND | WITH ANNEX XIV AND ANNEX XVII OF REACH | DIRECTIVE 76/769/EEC. A CERTIFICATE OF | COMPLIANCE IS REQUIRED UPON REQUEST. | ASSEMBLY SHALL MEET THE RoHS | COMMISSION DELEGATED DIRECTIVE (EU) | 2015/863 OF 31 MARCH  2015 AMENDING | ANNEX II TO DIRECTIVE 2011/65/EU. A | CERTIFICATE OF COMPLIANCE IS | REQUIRED UPON REQUEST.
User.19: TRACE WIDTH | (MILS) | IMPEDANCE | (OHMS) | TRACE SPACING | ---- | -- | 4.20 | 90 | 8.00 | DIFFERENTIAL PAIR
User.21: FIGURE | FINISHED_SIZE | 5.1 | DRILL CHART: TOP to L2_GND_1 | ALL UNITS ARE IN MILS | TOLERANCE_DRILL | +0.0/-5.1 | PLATED | QTY | 42 | TOTAL HOLES:
User.22: FIGURE | FINISHED_SIZE | 8.0 | 8.1 | 20.0 | 25.0 | DRILL CHART: TOP to BOTTOM | ALL UNITS ARE IN MILS | TOLERANCE_DRILL | +0.0/-8.0 | +0.0/-8.1 | +2.0/-2.0 | PLATED | NON-PLATED | QTY | 140 | 28 | 56 | 1 | 225 | TOTAL HOLES:
User.23: FIGURE | FINISHED_SIZE | 5.1 | DRILL CHART: L2_GND_1 to L3_INT_1 | ALL UNITS ARE IN MILS | TOLERANCE_DRILL | +0.0/-5.1 | PLATED | QTY | 33 | TOTAL HOLES:
User.25: FIGURE | FINISHED_SIZE | 5.1 | DRILL CHART: L3_INT_1 to L4_INT_2 | ALL UNITS ARE IN MILS | TOLERANCE_DRILL | +0.0/-5.1 | PLATED | QTY | 16 | TOTAL HOLES:
